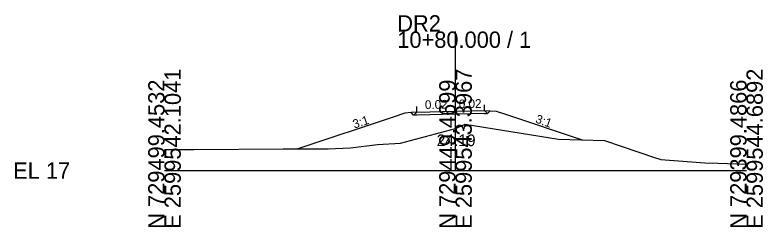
# Model space of a CAD drawing. Extents: x -26 to 1162, y -10 to 9515.
# Drawn here: x -25.7 to 102.8, y 3990.3 to 4026.7 of the extents above; entities that cross this region are included whole.
import ezdxf

# ---------------------------------------------------------------- set-up
doc = ezdxf.new("R2010")
doc.units = 0
for name, color, linetype in [('Exist Cross Section Cell', 7, 'Continuous'), ('Exist XS Center Line Elevation Label', 7, 'Continuous'), ('Exist XS Ground Line', 7, 'Continuous'), ('Prop XS Dump Level', 7, 'Continuous'), ('Prop XS EOT Tick Mark', 7, 'Continuous'), ('Prop XS Finish Grade', 7, 'Continuous'), ('Prop XS Finish Grade Earthwork', 7, 'Continuous'), ('Prop XS Finish Grade Pavement', 7, 'Continuous'), ('Prop XS Pvmt Edge Slope', 7, 'Continuous'), ('Prop XS SE Text', 7, 'Continuous'), ('Prop XS Side Slope Text', 7, 'Continuous'), ('Prop XS Subgrade Earthwork', 7, 'Continuous')]:
    doc.layers.add(name, color=color, linetype=linetype)

msp = doc.modelspace()

# ---------------------------------------------------------------- linework, layer by layer
at = {"layer": 'Exist Cross Section Cell'}
for p, q in [((50, 4000), (50, 4023.85)), ((0, 4000), (50, 4000)), ((50, 4000), (100, 4000))]:
    msp.add_line(p, q, dxfattribs=at)
at = {"layer": 'Exist XS Ground Line'}
msp.add_lwpolyline([(0, 4003.61), (5.07, 4003.61), (20.37, 4003.71), (28.13, 4003.74), (31.97, 4003.92), (36.57, 4004.44), (40.55, 4004.71), (50, 4007.19), (51.67, 4007.95), (67.71, 4005.41), (75.61, 4005.16), (84.18, 4002.21), (85.26, 4001.92), (92.82, 4001.31), (95.06, 4001.27), (100, 4001.12)], dxfattribs=at)
at = {"layer": 'Prop XS Dump Level'}
for p, q in [((50, 4010.16), (55, 4010.28)), ((43.33, 4010), (50, 4010.16))]:
    msp.add_line(p, q, dxfattribs=at)
at = {"layer": 'Prop XS EOT Tick Mark'}
for p, q in [((43.33, 4010), (43.33, 4011)), ((55, 4010.28), (55, 4011.28))]:
    msp.add_line(p, q, dxfattribs=at)
at = {"layer": 'Prop XS Finish Grade'}
for p, q in [((55, 4010.28), (55.95, 4010.24)), ((43.33, 4010), (42.37, 4009.93))]:
    msp.add_line(p, q, dxfattribs=at)
at = {"layer": 'Prop XS Finish Grade Earthwork'}
for p, q in [((55.95, 4010.24), (57, 4010.2)), ((39.45, 4009.23), (22.93, 4003.72)), ((41.3, 4009.84), (39.45, 4009.23)), ((42.37, 4009.93), (41.3, 4009.84)), ((57, 4010.2), (58.59, 4009.67)), ((58.59, 4009.67), (71.78, 4005.28))]:
    msp.add_line(p, q, dxfattribs=at)
at = {"layer": 'Prop XS Finish Grade Pavement'}
for p, q in [((50, 4010.16), (55, 4010.28)), ((43.33, 4010), (50, 4010.16))]:
    msp.add_line(p, q, dxfattribs=at)
at = {"layer": 'Prop XS Pvmt Edge Slope'}
for p, q in [((55, 4010.28), (55.49, 4009.79)), ((55.49, 4009.79), (55.95, 4010.24)), ((42.81, 4009.49), (42.37, 4009.93)), ((43.33, 4010), (42.81, 4009.49))]:
    msp.add_line(p, q, dxfattribs=at)
at = {"layer": 'Prop XS Subgrade Earthwork'}
for p, q in [((55.49, 4009.79), (55.95, 4010.24)), ((42.81, 4009.49), (42.37, 4009.93)), ((43.33, 4009.5), (42.81, 4009.49)), ((50, 4009.66), (43.33, 4009.5)), ((55, 4009.78), (50, 4009.66)), ((55, 4009.78), (55.49, 4009.79))]:
    msp.add_line(p, q, dxfattribs=at)

# ---------------------------------------------------------------- texts
at = {"layer": 'Exist Cross Section Cell'}
for s, p in [('DR2', (40, 4023.85)), ('10+80.000 / 1', (40, 4021.05)), ('EL 17', (-26, 3998.6))]:
    msp.add_text(s, height=2.8, dxfattribs=at).set_placement(p)
for s, p in [('E 2599542.1041', (2.8, 3990)), ('E 2599543.3967', (52.8, 3990)), ('E 2599544.6892', (102.8, 3990)), ('N 729499.4532', (0, 3990)), ('N 729449.4699', (50, 3990)), ('N 729399.4866', (100, 3990))]:
    msp.add_text(s, height=2.8, rotation=90, dxfattribs=at).set_placement(p)
at = {"layer": 'Exist XS Center Line Elevation Label'}
msp.add_text('24.19', height=2, dxfattribs=at).set_placement((46.76, 4004.19))
at = {"layer": 'Prop XS Dump Level'}
for p in [(41.3, 4009.8), (57, 4010.16)]:
    msp.add_text('Case1', height=0.04, dxfattribs=at).set_placement(p)
at = {"layer": 'Prop XS SE Text'}
for p in [(44.76, 4010.54), (50.59, 4010.67)]:
    msp.add_text('0.02', height=1.5, rotation=1.3433, dxfattribs=at).set_placement(p)
at = {"layer": 'Prop XS Side Slope Text'}
for rotation, p in [(18.1082, (32.62, 4007.19)), (340.3993, (63.61, 4008.26))]:
    msp.add_text('3:1', height=1.5, rotation=rotation, dxfattribs=at).set_placement(p)

doc.saveas('drawing.dxf')
